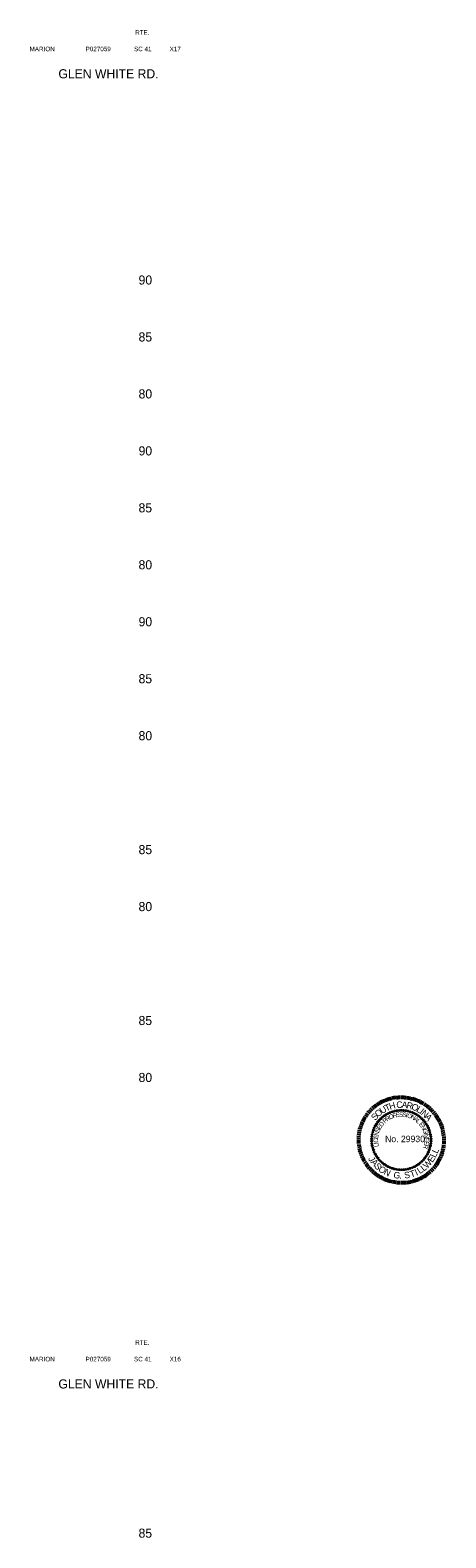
# Model space of a CAD drawing. Extents: x 1001 to 1184, y 1001 to 1562.
# Drawn here: x 1147.4 to 1183.9, y 1430 to 1562.3 of the extents above; entities that cross this region are included whole.
import ezdxf

# ---------------------------------------------------------------- set-up
doc = ezdxf.new("R2010")
doc.units = 0
for name, color, linetype in [('RD_HC_Cl', 7, 'Continuous'), ('RD_SHT_TX', 7, 'Continuous'), ('RD_TX_PEShield', 7, 'Continuous'), ('RD_XS_TX_Elev_EX', 7, 'Continuous')]:
    doc.layers.add(name, color=color, linetype=linetype)

# ---------------------------------------------------------------- blocks, each defined once
blk = doc.blocks.new('STILLWELL')
at = {"layer": 'RD_TX_PEShield'}
for p, q in [((-25.1, 24.7), (-27.4, 27.1)), ((-23.8, 25.9), (-26, 28.4)), ((-22.5, 27), (-24.5, 29.6)), ((-21.1, 28.1), (-23, 30.7)), ((-19.7, 29.1), (-21.5, 31.8)), ((-18.2, 30), (-19.9, 32.8)), ((-16.7, 30.8), (-18.2, 33.7)), ((-15.1, 31.6), (-16.5, 34.6)), ((-13.6, 32.3), (-14.8, 35.3)), ((-11.9, 32.9), (-13, 36)), ((-10.3, 33.4), (-11.2, 36.6)), ((-8.6, 33.9), (-9.4, 37.1)), ((-6.9, 34.3), (-7.5, 37.5)), ((-5.2, 34.6), (-5.7, 37.8)), ((-3.5, 34.8), (-3.8, 38)), ((-1.8, 34.9), (-1.9, 38.2)), ((0, 34.9), (0, 38.2)), ((1.7, 34.9), (1.9, 38.2)), ((3.4, 34.8), (3.7, 38)), ((5.2, 34.6), (5.6, 37.8)), ((6.9, 34.3), (7.5, 37.5)), ((8.6, 33.9), (9.3, 37.1)), ((10.2, 33.4), (11.2, 36.6)), ((11.9, 32.9), (13, 36)), ((13.5, 32.3), (14.7, 35.3)), ((15.1, 31.6), (16.5, 34.6)), ((16.6, 30.8), (18.2, 33.7)), ((18.2, 30), (19.8, 32.8)), ((19.6, 29.1), (21.4, 31.8)), ((21.1, 28.1), (23, 30.7)), ((22.4, 27), (24.5, 29.6)), ((23.8, 25.9), (25.9, 28.4)), ((25, 24.7), (27.3, 27.1)), ((-32.9, 13.4), (-35.9, 14.7)), ((-32.2, 15), (-35.1, 16.4)), ((-31.4, 16.5), (-34.2, 18.1)), ((-30.5, 18), (-33.3, 19.7)), ((-29.5, 19.4), (-32.2, 21.3)), ((-28.5, 20.9), (-31.1, 22.8)), ((-27.4, 22.2), (-29.9, 24.3)), ((-26.3, 23.5), (-28.7, 25.7)), ((26.2, 23.5), (28.6, 25.7)), ((27.4, 22.2), (29.9, 24.3)), ((28.5, 20.9), (31.1, 22.8)), ((29.5, 19.4), (32.2, 21.3)), ((30.4, 18), (33.2, 19.7)), ((31.3, 16.5), (34.2, 18.1)), ((32.1, 15), (35.1, 16.4)), ((32.9, 13.4), (35.9, 14.7)), ((-35.9, -0.1), (-39.2, 0)), ((-35.8, 1.7), (-39.1, 1.9)), ((-35.6, 3.4), (-38.9, 3.8)), ((-35.4, 5.1), (-38.6, 5.7)), ((-35.1, 6.8), (-38.2, 7.5)), ((-34.6, 8.5), (-37.8, 9.4)), ((-34.1, 10.2), (-37.2, 11.2)), ((-33.6, 11.8), (-36.6, 12.9)), ((33.5, 11.8), (36.6, 12.9)), ((34.1, 10.2), (37.2, 11.2)), ((34.6, 8.5), (37.7, 9.4)), ((35, 6.8), (38.2, 7.5)), ((35.3, 5.1), (38.5, 5.7)), ((35.6, 3.4), (38.8, 3.8)), ((35.7, 1.7), (39, 1.9)), ((35.8, -0.1), (39.1, 0)), ((-35.9, -1.8), (-39.2, -1.9)), ((-35.8, -3.5), (-39.1, -3.8)), ((-35.6, -5.3), (-38.9, -5.6)), ((-35.4, -7), (-38.6, -7.5)), ((-35.1, -8.7), (-38.2, -9.4)), ((-34.6, -10.4), (-37.8, -11.2)), ((-34.1, -12), (-37.2, -13)), ((34.1, -12), (37.2, -13)), ((34.6, -10.4), (37.7, -11.2)), ((35, -8.7), (38.2, -9.4)), ((35.3, -7), (38.5, -7.5)), ((35.6, -5.3), (38.8, -5.6)), ((35.7, -3.5), (39, -3.8)), ((35.8, -1.8), (39.1, -1.9)), ((-33.6, -13.6), (-36.6, -14.8)), ((-32.9, -15.3), (-35.9, -16.6)), ((-32.2, -16.8), (-35.1, -18.3)), ((-31.4, -18.4), (-34.2, -19.9)), ((-30.5, -19.9), (-33.3, -21.6)), ((-29.5, -21.3), (-32.2, -23.2)), ((-28.5, -22.7), (-31.1, -24.7)), ((-27.4, -24.1), (-29.9, -26.2)), ((-26.3, -25.4), (-28.7, -27.6)), ((26.2, -25.4), (28.6, -27.6)), ((27.4, -24.1), (29.9, -26.2)), ((28.5, -22.7), (31.1, -24.7)), ((29.5, -21.3), (32.2, -23.2)), ((30.4, -19.9), (33.2, -21.6)), ((31.3, -18.4), (34.2, -19.9)), ((32.1, -16.8), (35.1, -18.3)), ((32.9, -15.3), (35.9, -16.6)), ((33.5, -13.6), (36.6, -14.8)), ((-25.1, -26.6), (-27.4, -28.9)), ((-23.8, -27.8), (-26, -30.2)), ((-22.5, -28.9), (-24.5, -31.4)), ((-21.1, -29.9), (-23, -32.6)), ((-19.7, -30.9), (-21.5, -33.7)), ((-18.2, -31.8), (-19.9, -34.7)), ((-16.7, -32.7), (-18.2, -35.6)), ((-15.1, -33.5), (-16.5, -36.4)), ((-13.6, -34.1), (-14.8, -37.2)), ((-11.9, -34.8), (-13, -37.8)), ((-10.3, -35.3), (-11.2, -38.4)), ((-8.6, -35.8), (-9.4, -38.9)), ((-6.9, -36.1), (-7.5, -39.3)), ((-5.2, -36.4), (-5.7, -39.7)), ((-3.5, -36.6), (-3.8, -39.9)), ((-1.8, -36.8), (-1.9, -40)), ((0, -36.8), (0, -40.1)), ((1.7, -36.8), (1.9, -40)), ((3.4, -36.6), (3.7, -39.9)), ((5.2, -36.4), (5.6, -39.7)), ((6.9, -36.1), (7.5, -39.3)), ((8.6, -35.8), (9.3, -38.9)), ((10.2, -35.3), (11.2, -38.4)), ((11.9, -34.8), (13, -37.8)), ((13.5, -34.1), (14.7, -37.2)), ((15.1, -33.5), (16.5, -36.4)), ((16.6, -32.7), (18.2, -35.6)), ((18.2, -31.8), (19.8, -34.7)), ((19.6, -30.9), (21.4, -33.7)), ((21.1, -29.9), (23, -32.6)), ((22.4, -28.9), (24.5, -31.4)), ((23.8, -27.8), (25.9, -30.2)), ((25, -26.6), (27.3, -28.9))]:
    blk.add_line(p, q, dxfattribs=at)
for centre in [(-21.9, 13.2), (-20.7, 14.9), (-19.5, 16.4), (-18.1, 17.8), (-16.6, 19.2), (-15, 20.4), (-13.3, 21.5), (-11.6, 22.4), (-9.8, 23.2), (-7.9, 23.9), (-6, 24.4), (-4, 24.8), (-2, 25), (0, 25.1), (2, 25), (3.9, 24.8), (5.9, 24.4), (7.8, 23.9), (9.7, 23.2), (11.5, 22.4), (13.3, 21.5), (15, 20.4), (16.5, 19.2), (18, 17.8), (19.4, 16.4), (20.7, 14.9), (21.8, 13.2), (-26.1, 0.1), (-25.9, 2.1), (-25.6, 4), (-25.1, 6), (-24.5, 7.9), (-23.8, 9.7), (-22.9, 11.5), (22.9, 11.5), (23.7, 9.7), (24.5, 7.9), (25.1, 6), (25.5, 4), (25.8, 2.1), (26, 0.1), (-26.1, -1.9), (-25.9, -3.9), (-25.6, -5.9), (-25.1, -7.8), (-24.5, -9.7), (-23.8, -11.6), (-22.9, -13.4), (22.9, -13.4), (23.7, -11.6), (24.5, -9.7), (25.1, -7.8), (25.5, -5.9), (25.8, -3.9), (26, -1.9), (-21.9, -15.1), (-20.7, -16.7), (-19.5, -18.3), (-18.1, -19.7), (-16.6, -21), (-15, -22.2), (-13.3, -23.3), (-11.6, -24.3), (-9.8, -25.1), (-7.9, -25.8), (-6, -26.3), (-4, -26.7), (-2, -26.9), (2, -26.9), (3.9, -26.7), (5.9, -26.3), (7.8, -25.8), (9.7, -25.1), (11.5, -24.3), (13.3, -23.3), (15, -22.2), (16.5, -21), (18, -19.7), (19.4, -18.3), (20.7, -16.7), (21.8, -15.1), (0, -27)]:
    blk.add_circle(centre, 0.49, dxfattribs=at)
for s, height, rotation, p in [('U', 5.68, 32.2152, (-16.9, 21.8)), ('T', 5.68, 23.5044, (-13.2, 24.1)), ('H', 5.68, 16.1357, (-9.9, 25.6)), ('C', 5.68, 4.076, (-4.2, 27.1)), ('A', 5.68, 355.3651, (0.1, 27.4)), ('R', 5.68, 347.3188, (4.1, 27.1)), ('O', 5.68, 338.6079, (8.3, 26.2)), ('L', 5.68, 329.226, (12.6, 24.4)), ('I', 5.68, 322.5218, (15.5, 22.8)), ('S', 5.68, 49.6435, (-22.9, 15.8)), ('O', 5.68, 41.5972, (-20.4, 18.8)), ('D', 3.92, 52.5376, (-17.1, 10.3)), ('P', 3.92, 41.0022, (-14.5, 13.5)), ('R', 3.92, 33.3057, (-12.5, 15.3)), ('O', 3.92, 24.9735, (-10, 16.9)), ('F', 3.92, 15.9995, (-7.1, 18.3)), ('E', 3.92, 8.9511, (-4.7, 19)), ('S', 3.92, 1.2546, (-1.9, 19.4)), ('S', 3.92, 353.558, (0.8, 19.5)), ('I', 3.92, 345.8615, (3.5, 19.2)), ('O', 3.92, 342.6583, (4.7, 19)), ('N', 3.92, 333.6842, (7.7, 18)), ('A', 3.92, 325.3521, (10.4, 16.7)), ('L', 3.92, 317.6555, (12.6, 15.1)), ('E', 3.92, 308.0396, (15.1, 12.8)), ('N', 5.68, 319.1729, (16.8, 21.8)), ('A', 5.68, 310.4621, (20.1, 19)), ('C', 3.92, 92.2915, (-20.4, -3.2)), ('E', 3.92, 83.9594, (-20.5, -0.2)), ('N', 3.92, 76.2628, (-20.2, 2.5)), ('S', 3.92, 67.9307, (-19.5, 5.4)), ('E', 3.92, 60.2341, (-18.5, 7.9)), ('N', 3.92, 300.343, (16.8, 10.6)), ('G', 3.92, 292.0109, (18.3, 8.1)), ('I', 3.92, 283.0368, (19.5, 5.1)), ('N', 3.92, 279.8336, (19.8, 4)), ('E', 3.92, 271.5014, (20.3, 1.1)), ('I', 3.92, 95.4947, (-20.2, -4.3)), ('L', 3.92, 101.9075, (-19.7, -6.6)), ('R', 3.92, 256.1083, (20.1, -4.4)), ('E', 3.92, 263.8049, (20.4, -1.7)), ('L', 5.68, 65.098, (30, -16.9)), ('L', 5.68, 65.098, (31.6, -13.3)), ('J', 5.68, 299.033, (-29.4, -17.3)), ('A', 5.68, 310.5887, (-27.2, -20.6)), ('S', 5.68, 310.5887, (-24.3, -24)), ('O', 5.68, 321.0072, (-20.8, -27.4)), ('N', 5.68, 333.4326, (-16, -30.8)), ('I', 5.68, 25.3991, (13.3, -32.2)), ('L', 5.68, 34.0644, (16.2, -30.9)), ('L', 5.68, 37.6708, (19.6, -28.7)), ('W', 5.68, 47.0518, (22.6, -26.4)), ('E', 5.68, 56.4327, (27.3, -21.1)), ('G', 5.68, 352.2045, (-7.2, -34.2)), ('.', 5.68, 0.8698, (-1.8, -34.9)), ('S', 5.68, 8.0826, (2.9, -34.8)), ('T', 5.68, 18.9019, (8.5, -33.9))]:
    blk.add_text(s, height=height, rotation=rotation, dxfattribs=at).set_placement(p)
blk.add_text('No. 29930', height=5.68, dxfattribs=at).set_placement((-14.3, -2.8))

msp = doc.modelspace()

# ---------------------------------------------------------------- block references
at = {"layer": 'RD_HC_Cl', "xscale": 0.1, "yscale": 0.10000000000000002}
msp.add_blockref('STILLWELL', (1180, 1465), dxfattribs=at)

# ---------------------------------------------------------------- texts
at = {"layer": 'RD_SHT_TX'}
for s, height, p in [('RTE.', 0.4, (1156.62, 1561.93)), ('MARION', 0.4, (1147.35, 1560.48)), ('P027059', 0.4, (1152.27, 1560.48)), ('SC 41', 0.4, (1156.52, 1560.48)), ('X17', 0.4, (1159.65, 1560.48)), ('GLEN WHITE RD.', 0.8, (1149.88, 1558.1)), ('RTE.', 0.4, (1156.62, 1446.93)), ('MARION', 0.4, (1147.35, 1445.48)), ('P027059', 0.4, (1152.27, 1445.48)), ('SC 41', 0.4, (1156.52, 1445.48)), ('X16', 0.4, (1159.65, 1445.48)), ('GLEN WHITE RD.', 0.8, (1149.88, 1443.1))]:
    msp.add_text(s, height=height, dxfattribs=at).set_placement(p)
at = {"layer": 'RD_XS_TX_Elev_EX'}
for s, p in [('90', (1156.92, 1540)), ('85', (1156.92, 1535)), ('80', (1156.92, 1530)), ('90', (1156.92, 1525)), ('85', (1156.92, 1520)), ('80', (1156.92, 1515)), ('90', (1156.92, 1510)), ('85', (1156.92, 1505)), ('80', (1156.92, 1500)), ('85', (1156.92, 1490)), ('80', (1156.92, 1485)), ('85', (1156.92, 1475)), ('80', (1156.92, 1470)), ('85', (1156.92, 1430))]:
    msp.add_text(s, height=0.8, dxfattribs=at).set_placement(p)

doc.saveas('drawing.dxf')
